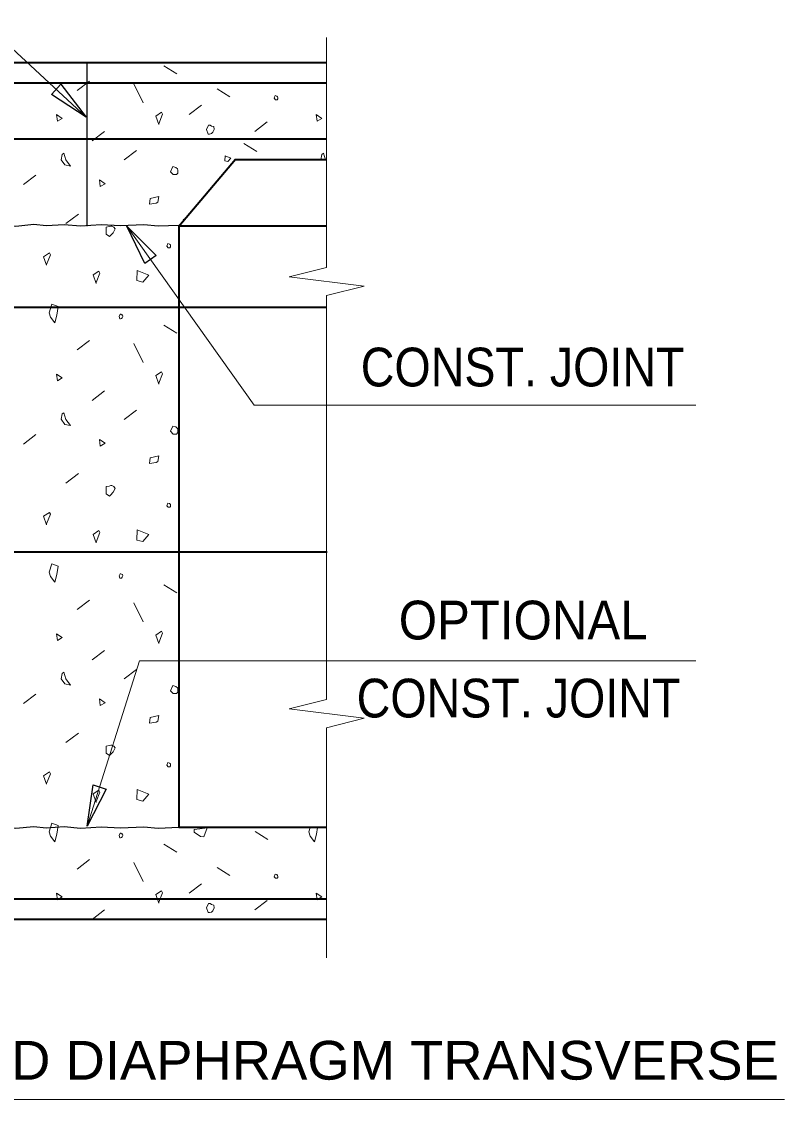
# Model space of a CAD drawing. Extents: x 0 to 34, y 0 to 23.4.
# Drawn here: x 21.208 to 24.17, y 15.614 to 19.798 of the extents above; entities that cross this region are included whole.
import ezdxf

# ---------------------------------------------------------------- set-up
doc = ezdxf.new("R2010")
doc.units = 0
doc.header["$LTSCALE"] = 0.062
for name, color, linetype, lineweight in [('1', 7, 'Continuous', 40), ('3', 7, 'Continuous', 35), ('4', 7, 'Continuous', 13), ('7', 7, 'Continuous', 13)]:
    doc.layers.add(name, color=color, linetype=linetype, lineweight=lineweight)

msp = doc.modelspace()

# ---------------------------------------------------------------- linework, layer by layer
at = {"layer": '1', "lineweight": 13}
for p, q in [((22.39245, 18.84359), (22.39245, 19.73682)), ((22.39245, 17.16651), (22.39245, 18.73422)), ((22.39245, 16.16391), (22.39245, 17.05714))]:
    msp.add_line(p, q, dxfattribs=at)
at = {"layer": '1'}
for p, q in [((22.39245, 19.63786), (18.03828, 19.63786)), ((21.81849, 19.00453), (22.03833, 19.26443)), ((22.39245, 19.26182), (22.0362, 19.26182)), ((22.39245, 16.66911), (21.81849, 16.66911)), ((22.39245, 16.31286), (18.03828, 16.31286))]:
    msp.add_line(p, q, dxfattribs=at)
at = {"layer": '1', "lineweight": 25}
msp.add_line((21.46224, 19.63786), (21.46224, 19.00453), dxfattribs=at)
for points in [[(21.81849, 19.00667), (21.73922, 19.00339), (21.68234, 19.0088), (21.59208, 19.00464), (21.5175, 19.00906), (21.43708, 19.00365), (21.37427, 19.00927), (21.30365, 19.00464), (21.25656, 19.01), (21.18594, 19.00292), (21.13687, 19.00927), (21.10599, 19.00667)], [(21.81849, 16.66911), (21.73922, 16.66583), (21.68234, 16.67125), (21.59208, 16.66708), (21.5175, 16.67151), (21.43708, 16.66609), (21.37427, 16.67172), (21.30365, 16.66708), (21.25656, 16.67245), (21.18594, 16.66536), (21.13687, 16.67172), (21.10599, 16.66911)]]:
    msp.add_lwpolyline(points, dxfattribs=at)
at = {"layer": '1'}
msp.add_lwpolyline([(22.39245, 19.00453), (21.81849, 19.00453), (21.81849, 16.66911)], dxfattribs=at)
at = {"layer": '1', "lineweight": 13}
for points in [[(22.39245, 18.84359), (22.24661, 18.80714), (22.53828, 18.77068), (22.39245, 18.73422)], [(22.39245, 17.16651), (22.24661, 17.13005), (22.53828, 17.09359), (22.39245, 17.05714)]]:
    msp.add_lwpolyline(points, dxfattribs=at)
at = {"layer": '3'}
for p, q in [((22.39245, 19.5587), (18.03828, 19.5587)), ((22.39245, 19.34099), (18.03828, 19.34099)), ((22.39245, 18.68786), (18.03828, 18.68786)), ((22.39443, 17.73786), (18.03828, 17.73786)), ((22.39245, 16.39203), (18.03828, 16.39203))]:
    msp.add_line(p, q, dxfattribs=at)
at = {"layer": '4'}
for p, q in [((20.8763, 19.96599), (21.45953, 19.42641)), ((22.11115, 18.30854), (21.61646, 19.00453)), ((22.11115, 18.30854), (23.82594, 18.30854)), ((21.66661, 17.31687), (21.46359, 16.67438)), ((21.66661, 17.31687), (23.82594, 17.31687)), ((20.16708, 15.61406), (24.17005, 15.61406))]:
    msp.add_line(p, q, dxfattribs=at)
at = {"layer": '4', "lineweight": 25}
for points in [[(21.32396, 19.51547), (21.36021, 19.55464), (21.45953, 19.42641)], [(21.73089, 18.88958), (21.6874, 18.85865), (21.61646, 19.00453)], [(21.48635, 16.835), (21.53724, 16.81891), (21.46359, 16.67438)]]:
    msp.add_lwpolyline(points, close=True, dxfattribs=at)
at = {"layer": '7'}
for p, q in [((21.76125, 19.62688), (21.81073, 19.59563)), ((21.47219, 19.56719), (21.42406, 19.53057)), ((21.64375, 19.55609), (21.68042, 19.48255)), ((21.9676, 19.53656), (22.01708, 19.50531)), ((21.90714, 19.47344), (21.85901, 19.43682)), ((22.16177, 19.40844), (22.11365, 19.37182)), ((21.53052, 19.37151), (21.4824, 19.3349)), ((21.65479, 19.29755), (21.60667, 19.26094)), ((22.07182, 19.32448), (22.1213, 19.29323)), ((22.37458, 19.2826), (22.37052, 19.26198)), ((21.2637, 19.20198), (21.21557, 19.16536)), ((21.42875, 19.05083), (21.38063, 19.01422)), ((21.83552, 19.0312), (21.83911, 19.02891)), ((21.76125, 18.61953), (21.81073, 18.58828)), ((21.47219, 18.55984), (21.42406, 18.52323)), ((21.64375, 18.54875), (21.68042, 18.47521)), ((21.53052, 18.36417), (21.4824, 18.32755)), ((21.65479, 18.29021), (21.60667, 18.25359)), ((21.2637, 18.19464), (21.21557, 18.15802)), ((21.42875, 18.04349), (21.38063, 18.00688)), ((21.76125, 17.61219), (21.81073, 17.58094)), ((21.47219, 17.5525), (21.42406, 17.51589)), ((21.64375, 17.54141), (21.68042, 17.46786)), ((21.53052, 17.35682), (21.4824, 17.32021)), ((21.65479, 17.28286), (21.60667, 17.24625)), ((21.2637, 17.18729), (21.21557, 17.15068)), ((21.42875, 17.03615), (21.38063, 16.99953)), ((22.11495, 16.65391), (22.16437, 16.6226)), ((21.76125, 16.60484), (21.81073, 16.57359)), ((21.47219, 16.54516), (21.42406, 16.50854)), ((21.64375, 16.53406), (21.68042, 16.46052)), ((21.9676, 16.51453), (22.01708, 16.48328)), ((21.90714, 16.45141), (21.85901, 16.41479)), ((22.16177, 16.38641), (22.11365, 16.34979)), ((21.53052, 16.34948), (21.4824, 16.31286))]:
    msp.add_line(p, q, dxfattribs=at)
for points in [[(22.19323, 19.51047), (22.18859, 19.50031), (22.19401, 19.49469), (22.20063, 19.49469), (22.20333, 19.49766), (22.20333, 19.50307), (22.20245, 19.50573), (22.19958, 19.5087)], [(21.34375, 19.43672), (21.34745, 19.41089), (21.36594, 19.42198)], [(21.72979, 19.4313), (21.7412, 19.39807), (21.7412, 19.40167), (21.75589, 19.43865), (21.75214, 19.44599)], [(22.35214, 19.43672), (22.35583, 19.41089), (22.37432, 19.42198)], [(21.92641, 19.37958), (21.93224, 19.36115), (21.93755, 19.36115), (21.94505, 19.36297), (21.95047, 19.36833), (21.95583, 19.37958), (21.95432, 19.39052), (21.94505, 19.39245), (21.94115, 19.39625), (21.9338, 19.39625)], [(21.3662, 19.2826), (21.36214, 19.26187), (21.37589, 19.24156), (21.39891, 19.23703), (21.38052, 19.26141), (21.37266, 19.28672)], [(21.99813, 19.27714), (21.99724, 19.25734), (22.00917, 19.25458), (22.02068, 19.26792)], [(21.79516, 19.23552), (21.78589, 19.21531), (21.79672, 19.20406), (21.80995, 19.20406), (21.81536, 19.20995), (21.81536, 19.22073), (21.81354, 19.22604), (21.80781, 19.23198)], [(21.51036, 19.18359), (21.51406, 19.15776), (21.53255, 19.16885)], [(21.70818, 19.11193), (21.70448, 19.0899), (21.73031, 19.09359), (21.7376, 19.09719), (21.7413, 19.11932)], [(21.53693, 19.00052), (21.53693, 18.9726), (21.54958, 18.96365), (21.55344, 18.96724), (21.56427, 18.97833), (21.57167, 18.99313), (21.5663, 19.00052), (21.55891, 19.00406), (21.55531, 19.00406), (21.54807, 19.00203)], [(21.77672, 18.93615), (21.77208, 18.92604), (21.7775, 18.92042), (21.78411, 18.92042), (21.78682, 18.92333), (21.78682, 18.92875), (21.78594, 18.93141), (21.78307, 18.93438)], [(21.29401, 18.88536), (21.30536, 18.85214), (21.30536, 18.85568), (21.32016, 18.89271), (21.31641, 18.90005)], [(21.4862, 18.81464), (21.4976, 18.78146), (21.4976, 18.785), (21.51229, 18.82203), (21.50854, 18.82938)], [(21.6575, 18.83224), (21.65573, 18.79266), (21.67964, 18.78708), (21.70266, 18.8138)], [(21.32635, 18.70099), (21.31516, 18.66786), (21.32083, 18.6513), (21.3374, 18.62917), (21.34474, 18.65865), (21.35026, 18.69182)], [(21.58677, 18.65375), (21.58969, 18.64453), (21.59234, 18.64453), (21.59609, 18.64547), (21.5988, 18.64813), (21.60146, 18.65375), (21.60073, 18.65927), (21.59609, 18.66021), (21.59411, 18.66214), (21.59047, 18.66214)], [(21.34375, 18.42938), (21.34745, 18.40354), (21.36594, 18.41464)], [(21.72979, 18.42396), (21.7412, 18.39073), (21.7412, 18.39432), (21.75589, 18.4313), (21.75214, 18.43865)], [(21.3662, 18.27526), (21.36214, 18.25453), (21.37589, 18.23422), (21.39891, 18.22969), (21.38052, 18.25406), (21.37266, 18.27938)], [(21.79516, 18.22818), (21.78589, 18.20797), (21.79672, 18.19672), (21.80995, 18.19672), (21.81536, 18.2026), (21.81536, 18.21339), (21.81354, 18.2187), (21.80781, 18.22464)], [(21.51036, 18.17625), (21.51406, 18.15042), (21.53255, 18.16151)], [(21.70818, 18.10458), (21.70448, 18.08255), (21.73031, 18.08625), (21.7376, 18.08984), (21.7413, 18.11198)], [(21.53693, 17.99318), (21.53693, 17.96526), (21.54958, 17.9563), (21.55344, 17.9599), (21.56427, 17.97099), (21.57167, 17.98578), (21.5663, 17.99318), (21.55891, 17.99672), (21.55531, 17.99672), (21.54807, 17.99469)], [(21.77672, 17.9288), (21.77208, 17.9187), (21.7775, 17.91307), (21.78411, 17.91307), (21.78682, 17.91599), (21.78682, 17.92141), (21.78594, 17.92406), (21.78307, 17.92703)], [(21.29401, 17.87802), (21.30536, 17.84479), (21.30536, 17.84833), (21.32016, 17.88536), (21.31641, 17.89271)], [(21.6575, 17.8249), (21.65573, 17.78531), (21.67964, 17.77974), (21.70266, 17.80646)], [(21.4862, 17.80729), (21.4976, 17.77411), (21.4976, 17.77766), (21.51229, 17.81469), (21.50854, 17.82203)], [(21.32635, 17.69365), (21.31516, 17.66052), (21.32083, 17.64396), (21.3374, 17.62182), (21.34474, 17.6513), (21.35026, 17.68448)], [(21.58677, 17.64641), (21.58969, 17.63719), (21.59234, 17.63719), (21.59609, 17.63813), (21.5988, 17.64078), (21.60146, 17.64641), (21.60073, 17.65193), (21.59609, 17.65286), (21.59411, 17.65479), (21.59047, 17.65479)], [(21.34375, 17.42203), (21.34745, 17.3962), (21.36594, 17.40729)], [(21.72979, 17.41661), (21.7412, 17.38339), (21.7412, 17.38698), (21.75589, 17.42396), (21.75214, 17.4313)], [(21.3662, 17.26792), (21.36214, 17.24719), (21.37589, 17.22687), (21.39891, 17.22234), (21.38052, 17.24672), (21.37266, 17.27203)], [(21.79516, 17.22083), (21.78589, 17.20063), (21.79672, 17.18938), (21.80995, 17.18938), (21.81536, 17.19526), (21.81536, 17.20604), (21.81354, 17.21135), (21.80781, 17.21729)], [(21.51036, 17.16891), (21.51406, 17.14307), (21.53255, 17.15417)], [(21.70818, 17.09724), (21.70448, 17.07521), (21.73031, 17.07891), (21.7376, 17.0825), (21.7413, 17.10464)], [(21.53693, 16.98583), (21.53693, 16.95792), (21.54958, 16.94896), (21.55344, 16.95255), (21.56427, 16.96365), (21.57167, 16.97844), (21.5663, 16.98583), (21.55891, 16.98938), (21.55531, 16.98938), (21.54807, 16.98734)], [(21.77672, 16.92146), (21.77208, 16.91135), (21.7775, 16.90573), (21.78411, 16.90573), (21.78682, 16.90865), (21.78682, 16.91406), (21.78594, 16.91672), (21.78307, 16.91969)], [(21.29401, 16.87068), (21.30536, 16.83745), (21.30536, 16.84099), (21.32016, 16.87802), (21.31641, 16.88536)], [(21.4862, 16.79995), (21.4976, 16.76677), (21.4976, 16.77031), (21.51229, 16.80734), (21.50854, 16.81469)], [(21.6575, 16.81755), (21.65573, 16.77797), (21.67964, 16.7724), (21.70266, 16.79911)], [(21.32635, 16.6863), (21.31516, 16.65318), (21.32083, 16.63661), (21.3374, 16.61448), (21.34474, 16.64396), (21.35026, 16.67714)], [(21.90099, 16.66437), (21.87891, 16.6625), (21.87891, 16.65146), (21.90286, 16.63495), (21.91583, 16.63307), (21.92875, 16.66802)], [(21.58677, 16.63906), (21.58969, 16.62984), (21.59234, 16.62984), (21.59609, 16.63078), (21.5988, 16.63344), (21.60146, 16.63906), (21.60073, 16.64458), (21.59609, 16.64552), (21.59411, 16.64745), (21.59047, 16.64745)], [(22.19323, 16.48844), (22.18859, 16.47828), (22.19401, 16.47266), (22.20063, 16.47266), (22.20333, 16.47563), (22.20333, 16.48104), (22.20245, 16.4837), (22.19958, 16.48667)], [(21.34375, 16.41469), (21.34745, 16.38885), (21.36594, 16.39995)], [(21.72979, 16.40927), (21.7412, 16.37604), (21.7412, 16.37964), (21.75589, 16.41661), (21.75214, 16.42396)], [(22.35214, 16.41469), (22.35583, 16.38885), (22.37432, 16.39995)], [(21.92641, 16.35755), (21.93224, 16.33911), (21.93755, 16.33911), (21.94505, 16.34094), (21.95047, 16.3463), (21.95583, 16.35755), (21.95432, 16.36849), (21.94505, 16.37042), (21.94115, 16.37422), (21.9338, 16.37422)]]:
    msp.add_lwpolyline(points, close=True, dxfattribs=at)
for points in [[(22.38875, 19.26187), (22.38104, 19.28672), (22.37458, 19.2826)], [(22.32891, 16.66911), (22.32354, 16.65318), (22.32922, 16.63661), (22.34578, 16.61448), (22.35313, 16.64396), (22.35729, 16.66911)]]:
    msp.add_lwpolyline(points, dxfattribs=at)

# ---------------------------------------------------------------- texts
at = {"layer": '4'}
for s, width, p in [('CONST. JOINT', 0.9, (22.5251, 18.38182)), ('OPTIONAL', 0.95, (22.67271, 17.39969)), ('CONST. JOINT', 0.9, (22.50922, 17.09677)), ('SLAB AND DIAPHRAGM TRANSVERSE', 1.05, (20.27589, 15.69089))]:
    msp.add_text(s, height=0.1504, dxfattribs=dict(at, width=width)).set_placement(p)

doc.saveas('drawing.dxf')
